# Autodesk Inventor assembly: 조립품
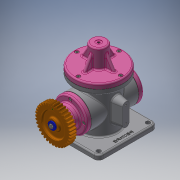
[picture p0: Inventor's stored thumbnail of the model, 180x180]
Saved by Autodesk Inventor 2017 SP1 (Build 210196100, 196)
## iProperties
Part Number: 조립품
Material: 일반
Document SubType Name: Assembly
Designer: 00-00
Mass: 1721.03 g
Surface Area: 2327.83 cm^2
Volume: 694.998 cm^3
Density: 2.47631 g/cm^3
Author: 00-00
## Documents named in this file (21)
- C:\Users\00-00\Desktop\601206V1010\조립품.iam
- C:\Users\00-00\Desktop\601206V1010\E-링.ipt
- C:\Users\00-00\Desktop\601206V1010\가변스프링.ipt
- C:\Users\00-00\Desktop\601206V1010\개스킷 A.ipt
- C:\Users\00-00\Desktop\601206V1010\개스킷 B.ipt
- C:\Users\00-00\Desktop\601206V1010\덮개.ipt
- C:\Users\00-00\Desktop\601206V1010\뒤커버.ipt
- C:\Users\00-00\Desktop\601206V1010\링크.ipt
- C:\Users\00-00\Desktop\601206V1010\베어링 17 x 40 x 12.ipt
- C:\Users\00-00\Desktop\601206V1010\본체.ipt
- C:\Users\00-00\Desktop\601206V1010\볼트 M4 x 10.ipt
- C:\Users\00-00\Desktop\601206V1010\스퍼기어.ipt
- C:\Users\00-00\Desktop\601206V1010\슬라이더.ipt
- C:\Users\00-00\Desktop\601206V1010\앞커버.ipt
- C:\Users\00-00\Desktop\601206V1010\오일 실 17 30 8.ipt
- C:\Users\00-00\Desktop\601206V1010\와셔 4x16.ipt
- C:\Users\00-00\Desktop\601206V1010\육각 소켓 머리 볼트 M4 x 10.ipt
- C:\Users\00-00\Desktop\601206V1010\클레비스 핀 6 x 22.ipt
- 클레비스 핀 6 x 22.ipt
- C:\Users\00-00\Desktop\601206V1010\키 4 x 4 x 18.ipt
- C:\Users\00-00\Desktop\601206V1010\편심축.ipt
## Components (5 placed, 4 different names)
1. E-링:1
2. 가변스프링:1
3. 개스킷 A:1
4. 개스킷 B:1
5. 개스킷 A:2
